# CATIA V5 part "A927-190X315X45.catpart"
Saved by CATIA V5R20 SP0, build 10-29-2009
Part number: A927-190X315X45
Source: Unknown
Property "A": "90.000"
Property "ARTICLENO": "A927-190X315X45"
Property "BOMINFO": "A927-190X315X45"
Property "CODE": "A927-190X315X45"
Property "CREATOR": "CADENAS GmbH"
Property "D": "22.000"
Property "D1": "33.000"
Property "F": "36.000"
Property "FORM": "B"
Property "L": "315.000"
Property "L1": "150.000"
Property "L2": "40.000"
Property "L3": "80.000"
Property "LINA": "A927-190X315X45"
Property "NB": "A927-190X315X45"
Property "NBSYN": "$CODE."
Property "NN": "A927"
Property "NT": "VDI 3387 Removable Die Heels, steel and self-lubricating"
Property "R": "31.500"
Property "S": "45.000"
Property "SUPPLIER": "CF"
Property "T": "25.500"
Property "W": "190.000"
Bounding box of the stored display mesh (mm): x -95 to 95, y 0 to 315, z -45 to 0
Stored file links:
  C:\Users\borellobunino\Desktop\3D X SITO CF\A927\GSB_OILLESS_G2290519031545\CATIAV5\A927-190X315X45.catpart
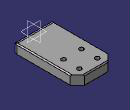
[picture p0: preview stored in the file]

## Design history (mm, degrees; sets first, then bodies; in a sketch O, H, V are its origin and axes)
Body1 "Geometry.1" (main body)
  Solid1 "A927-190X315X45.catpart": solid without history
